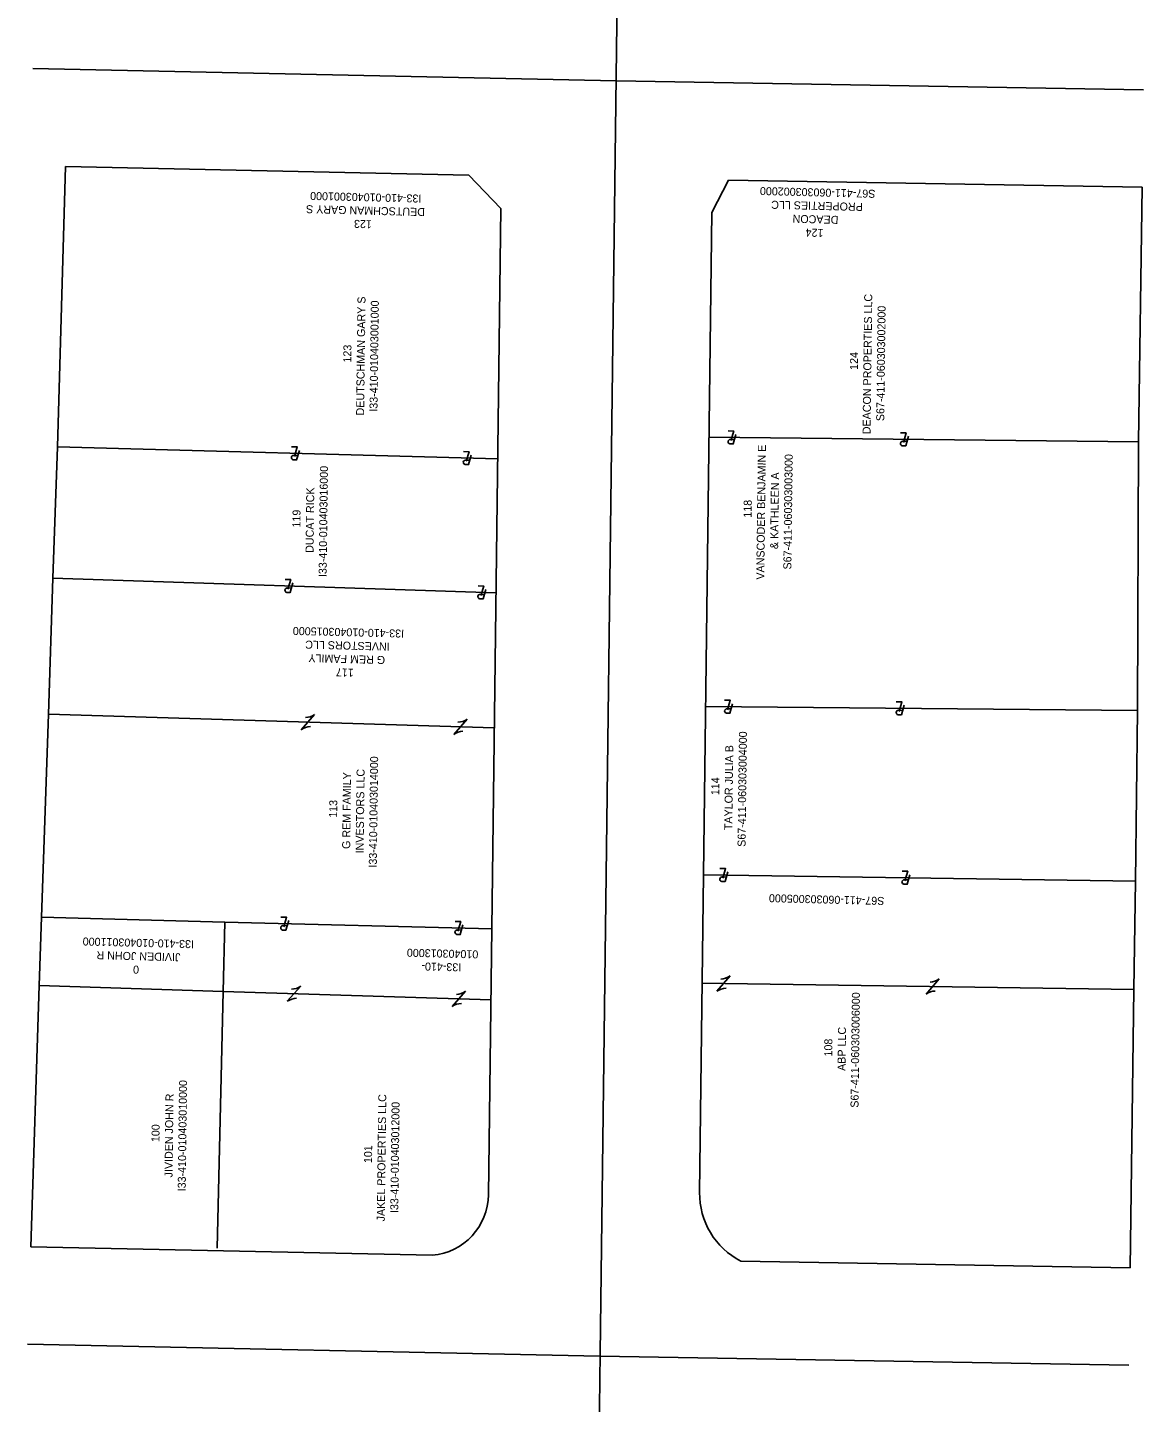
# Model space of a CAD drawing. Extents: x 1652206 to 1653153, y 604222 to 614600.
# Drawn here: x 1652374.5 to 1652718.2, y 606857 to 607280.6 of the extents above; entities that cross this region are included whole.
import ezdxf

# ---------------------------------------------------------------- set-up
doc = ezdxf.new("R2010")
doc.units = 0
for name, color, linetype in [('_CIVIL_CONSTRUCTION', 7, 'Continuous'), ('GE_P_Alignment_100_Bearings', 7, 'Continuous'), ('GE_P_Alignment_100_Cardinal_Points', 7, 'Continuous'), ('GE_P_Alignment_100_Distances', 7, 'Continuous'), ('GE_P_Alignment_100_Stations', 7, 'Continuous')]:
    doc.layers.add(name, color=color, linetype=linetype)

msp = doc.modelspace()

# ---------------------------------------------------------------- linework, layer by layer
at = {"layer": '_CIVIL_CONSTRUCTION'}
for p, q in [((1652550.86, 606872.07), (1652575.14, 608815.48)), ((1652555.76, 607264.17), (1652376.13, 607268)), ((1652555.76, 607264.17), (1652718.21, 607261.41)), ((1652516.96, 604222.43), (1652550.86, 606872.07))]:
    msp.add_line(p, q, dxfattribs=at)
at = {"layer": 'GE_P_Alignment_100_Bearings'}
for p, q in [((1652383.72, 607151.45), (1652386.16, 607237.78)), ((1652717.77, 607231.42), (1652716.63, 607153.03)), ((1652382.34, 607111.01), (1652383.72, 607151.45)), ((1652383.72, 607151.45), (1652519.3, 607147.7)), ((1652716.63, 607153.03), (1652584.39, 607154.4)), ((1652592.24, 607153.69), (1652590.94, 607153.71)), ((1652591.44, 607154.33), (1652591.44, 607154.33)), ((1652645.34, 607153.14), (1652644.05, 607153.16)), ((1652644.55, 607153.78), (1652644.55, 607153.78)), ((1652716.63, 607153.03), (1652716.34, 607070.25)), ((1652457.77, 607148.78), (1652456.48, 607148.81)), ((1652456.99, 607149.42), (1652456.99, 607149.42)), ((1652510.72, 607147.32), (1652509.42, 607147.35)), ((1652509.93, 607147.96), (1652509.93, 607147.96)), ((1652380.96, 607069.07), (1652382.34, 607111.01)), ((1652382.34, 607111.01), (1652518.78, 607106.43)), ((1652455.78, 607107.92), (1652454.49, 607107.96)), ((1652455, 607108.57), (1652455, 607108.57)), ((1652515.22, 607105.92), (1652513.92, 607105.96)), ((1652514.44, 607106.57), (1652514.44, 607106.57)), ((1652716.34, 607070.25), (1652583.35, 607071.4)), ((1652591.19, 607070.71), (1652589.89, 607070.72)), ((1652590.39, 607071.34), (1652590.39, 607071.34)), ((1652643.24, 607070.89), (1652643.24, 607070.89)), ((1652378.84, 607006.51), (1652380.96, 607069.07)), ((1652380.96, 607069.07), (1652518.26, 607064.87)), ((1652462.93, 607068.96), (1652458.78, 607064.29)), ((1652460.86, 607066.62), (1652460.86, 607066.62)), ((1652509.92, 607067.53), (1652505.77, 607062.85)), ((1652644.03, 607070.25), (1652642.74, 607070.27)), ((1652716.34, 607070.25), (1652715.7, 607017.59)), ((1652507.85, 607065.19), (1652507.85, 607065.19)), ((1652715.7, 607017.59), (1652582.7, 607019.62)), ((1652589.72, 607018.89), (1652588.42, 607018.91)), ((1652588.92, 607019.53), (1652588.92, 607019.53)), ((1652645.81, 607018.03), (1652644.52, 607018.05)), ((1652645.02, 607018.67), (1652645.02, 607018.67)), ((1652715.7, 607017.59), (1652715.27, 606984.29)), ((1652378.08, 606985.45), (1652378.84, 607006.51)), ((1652378.84, 607006.51), (1652435.22, 607005.01)), ((1652434.72, 606983.63), (1652435.22, 607005.01)), ((1652435.22, 607005.01), (1652517.49, 607002.93)), ((1652454.48, 607003.9), (1652453.18, 607003.93)), ((1652453.69, 607004.54), (1652453.69, 607004.54)), ((1652507.37, 607003.19), (1652507.37, 607003.19)), ((1652508.15, 607002.55), (1652506.86, 607002.58)), ((1652715.27, 606984.29), (1652582.29, 606986.15)), ((1652590.86, 606988.43), (1652586.79, 606983.69)), ((1652588.83, 606986.06), (1652588.83, 606986.06)), ((1652655.31, 606987.53), (1652651.24, 606982.78)), ((1652375.47, 606904.99), (1652378.08, 606985.45)), ((1652378.08, 606985.45), (1652434.72, 606983.63)), ((1652432.94, 606904.59), (1652434.72, 606983.63)), ((1652434.72, 606983.63), (1652517.22, 606981.04)), ((1652458.66, 606985.28), (1652454.51, 606980.6)), ((1652456.58, 606982.94), (1652456.58, 606982.94)), ((1652509.43, 606983.68), (1652505.28, 606979.01)), ((1652653.27, 606985.15), (1652653.27, 606985.15)), ((1652715.27, 606984.29), (1652714.09, 606898.48)), ((1652507.36, 606981.35), (1652507.36, 606981.35))]:
    msp.add_line(p, q, dxfattribs=at)
for points in [[(1652591.16, 607153.37), (1652591.99, 607156.32), (1652590.24, 607156.34)], [(1652592.67, 607155.28), (1652591.86, 607152.32), (1652590.83, 607152.34)], [(1652644.27, 607152.82), (1652645.09, 607155.77), (1652643.35, 607155.79)], [(1652456.7, 607148.47), (1652457.57, 607151.4), (1652455.82, 607151.45)], [(1652645.78, 607154.73), (1652644.97, 607151.78), (1652643.93, 607151.79)], [(1652458.24, 607150.36), (1652457.37, 607147.41), (1652456.34, 607147.44)], [(1652509.64, 607147.01), (1652510.51, 607149.94), (1652508.77, 607149.99)], [(1652511.18, 607148.89), (1652510.32, 607145.95), (1652509.28, 607145.98)], [(1652454.7, 607107.62), (1652455.59, 607110.54), (1652453.85, 607110.6)], [(1652456.26, 607109.49), (1652455.37, 607106.56), (1652454.34, 607106.59)], [(1652514.14, 607105.62), (1652515.03, 607108.55), (1652513.28, 607108.61)], [(1652515.69, 607107.5), (1652514.81, 607104.56), (1652513.78, 607104.6)], [(1652590.12, 607070.39), (1652590.93, 607073.34), (1652589.19, 607073.35)], [(1652591.62, 607072.3), (1652590.81, 607069.34), (1652589.78, 607069.35)], [(1652642.96, 607069.93), (1652643.78, 607072.88), (1652642.03, 607072.89)], [(1652644.47, 607071.84), (1652643.66, 607068.88), (1652642.63, 607068.9)], [(1652588.64, 607018.57), (1652589.48, 607021.52), (1652587.73, 607021.54)], [(1652590.16, 607020.48), (1652589.33, 607017.53), (1652588.3, 607017.54)], [(1652644.74, 607017.71), (1652645.58, 607020.66), (1652643.83, 607020.68)], [(1652646.26, 607019.62), (1652645.43, 607016.67), (1652644.4, 607016.68)], [(1652453.4, 607003.59), (1652454.27, 607006.52), (1652452.52, 607006.57)], [(1652454.94, 607005.48), (1652454.08, 607002.53), (1652453.05, 607002.56)], [(1652507.07, 607002.24), (1652507.94, 607005.17), (1652506.19, 607005.22)], [(1652508.61, 607004.13), (1652507.76, 607001.18), (1652506.72, 607001.21)]]:
    msp.add_lwpolyline(points, dxfattribs=at)
for centre, radius, start, end in [((1652590.94, 607153.02), 0.69, 89.8782, 260.7353), ((1652644.04, 607152.47), 0.69, 89.8782, 260.7353), ((1652456.46, 607148.12), 0.69, 88.8893, 259.7465), ((1652509.41, 607146.66), 0.69, 88.8893, 259.7465), ((1652454.47, 607107.27), 0.69, 88.5484, 259.4056), ((1652513.9, 607105.28), 0.69, 88.5484, 259.4056), ((1652589.89, 607070.03), 0.69, 89.9741, 260.8312), ((1652459.9, 607073.36), 5.34, 271.9438, 304.5863), ((1652506.89, 607071.92), 5.34, 271.9438, 304.5863), ((1652642.74, 607069.58), 0.69, 89.9741, 260.8312), ((1652461.81, 607059.89), 5.34, 91.9438, 124.5863), ((1652508.8, 607058.46), 5.34, 91.9438, 124.5863), ((1652588.41, 607018.22), 0.69, 89.5927, 260.4498), ((1652644.51, 607017.36), 0.69, 89.5927, 260.4498), ((1652453.17, 607003.24), 0.69, 89.0287, 259.8858), ((1652506.84, 607001.89), 0.69, 89.0287, 259.8858), ((1652587.76, 606992.77), 5.34, 272.8908, 305.5334), ((1652652.21, 606991.87), 5.34, 272.8908, 305.5334), ((1652457.54, 606976.21), 5.34, 91.8966, 124.5392), ((1652455.63, 606989.67), 5.34, 271.8966, 304.5392), ((1652506.41, 606988.08), 5.34, 271.8966, 304.5392), ((1652589.9, 606979.34), 5.34, 92.8908, 125.5334), ((1652654.34, 606978.44), 5.34, 92.8908, 125.5334), ((1652508.31, 606974.61), 5.34, 91.8966, 124.5392)]:
    msp.add_arc(centre, radius, start, end, dxfattribs=at)
at = {"layer": 'GE_P_Alignment_100_Distances'}
for p, q in [((1652510.39, 607235.13), (1652386.16, 607237.78)), ((1652520.26, 607224.92), (1652510.39, 607235.13)), ((1652585.25, 607223.67), (1652590.38, 607233.58)), ((1652717.77, 607231.42), (1652590.38, 607233.58)), ((1652516.47, 606920.99), (1652520.26, 607224.92)), ((1652581.48, 606921.74), (1652585.25, 607223.67)), ((1652499.15, 606902.36), (1652375.47, 606904.99)), ((1652714.09, 606898.48), (1652594.22, 606900.52))]:
    msp.add_line(p, q, dxfattribs=at)
for centre, radius, start, end in [((1652497.53, 606921.23), 18.94, 274.9087, 359.2843), ((1652605.04, 606921.44), 23.56, 179.2843, 242.6619)]:
    msp.add_arc(centre, radius, start, end, dxfattribs=at)
at = {"layer": 'GE_P_Alignment_100_Stations'}
for q in [(1652374.5, 606875.01), (1652713.68, 606868.48)]:
    msp.add_line((1652550.8, 606871.25), q, dxfattribs=at)

# ---------------------------------------------------------------- texts
at = {"layer": 'GE_P_Alignment_100_Cardinal_Points'}
for s, height, rotation, p in [('S67-411-060303002000', 2.4653, 178.565, (1652635.66, 607230.62)), ('I33-410-010403001000', 2.4653, 178.565, (1652495.84, 607229.14)), ('PROPERTIES LLC', 2.4653, 178.565, (1652631.78, 607226.57)), ('DEUTSCHMAN GARY S', 2.4653, 178.565, (1652496.94, 607225)), ('123', 2.465, 178.565, (1652480.59, 607221.25)), ('DEACON', 2.465, 178.565, (1652624.27, 607222.6)), ('124', 2.465, 178.565, (1652619.67, 607218.56)), ('DEUTSCHMAN GARY S', 2.4653, 89.2843, (1652478.15, 607161.1)), ('DEACON PROPERTIES LLC', 2.4653, 89.2843, (1652634.14, 607155.32)), ('I33-410-010403001000', 2.4653, 89.2843, (1652482.28, 607162.25)), ('S67-411-060303002000', 2.4653, 89.2843, (1652638.35, 607159.34)), ('123', 2.465, 89.2843, (1652474.2, 607177.4)), ('124', 2.465, 89.2843, (1652630.24, 607175.13)), ('VANSCODER BENJAMIN E ', 2.4653, 89.2843, (1652601.4, 607110.52)), ('S67-411-060303003000', 2.4653, 89.2843, (1652609.74, 607113.64)), ('I33-410-010403016000', 2.4653, 89.2843, (1652466.61, 607111.29)), ('& KATHLEEN A', 2.4653, 89.2843, (1652605.67, 607119.92)), ('DUCAT RICK', 2.465, 89.2843, (1652462.58, 607118.76)), ('118', 2.465, 89.2843, (1652597.49, 607129.59)), ('119', 2.465, 89.2843, (1652458.53, 607126.56)), ('I33-410-010403015000', 2.4653, 178.565, (1652490.51, 607095.11)), ('INVESTORS LLC', 2.4653, 178.565, (1652486.08, 607091.1)), ('G REM FAMILY', 2.4653, 178.565, (1652484.66, 607086.98)), ('117', 2.465, 178.565, (1652475.02, 607083.07)), ('S67-411-060303004000', 2.4653, 89.2843, (1652595.64, 607028.19)), ('TAYLOR JULIA B', 2.4653, 89.2843, (1652591.55, 607033.32)), ('I33-410-010403014000', 2.4653, 89.2843, (1652482.07, 607021.79)), ('G REM FAMILY ', 2.4653, 89.2843, (1652473.87, 607027.53)), ('INVESTORS LLC', 2.4653, 89.2843, (1652478, 607026.16)), ('114', 2.465, 89.2843, (1652587.53, 607044.1)), ('113', 2.465, 89.2843, (1652469.84, 607037.12)), ('S67-411-060303005000', 2.4653, 178.565, (1652638.43, 607012.73)), ('I33-410-010403011000', 2.4653, 178.565, (1652425.8, 606999.42)), ('JIVIDEN JOHN R', 2.4653, 178.565, (1652421.59, 606995.4)), ('010403013000', 2.4653, 178.565, (1652513.36, 606996.27)), ('0', 2.47, 178.565, (1652408.87, 606991.57)), ('I33-410-', 2.465, 178.565, (1652508.12, 606992.28)), ('S67-411-060303006000', 2.4653, 89.2843, (1652630.43, 606947.8)), ('108', 2.465, 89.2843, (1652622.32, 606963.57)), ('ABP LLC', 2.465, 89.2843, (1652626.42, 606959.15)), ('I33-410-010403010000', 2.4653, 89.2843, (1652423.21, 606922.04)), ('JIVIDEN JOHN R', 2.4653, 89.2843, (1652419.15, 606926.32)), ('JAKEL PROPERTIES LLC', 2.4653, 89.2843, (1652484.52, 606912.77)), ('I33-410-010403012000', 2.4653, 89.2843, (1652488.67, 606915.34)), ('100', 2.465, 89.2843, (1652415.13, 606937.19)), ('101', 2.465, 89.2843, (1652480.59, 606930.73))]:
    msp.add_text(s, height=height, rotation=rotation, dxfattribs=at).set_placement(p)

doc.saveas('drawing.dxf')
